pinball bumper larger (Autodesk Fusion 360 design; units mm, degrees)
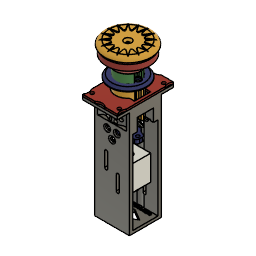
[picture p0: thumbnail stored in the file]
sketch "Base" plane through (0, 0, 0) normal (0, 0, 1) x axis (1, 0, 0)
  line L1 (-14, 14) -> (-14, 0)
  line L2 (14, 14) -> (-14, 14)
  line L3 (14, -14) -> (14, 14)
  line L4 (-14, -14) -> (14, -14)
  line L5 (-14, 0) -> (-14, -14)
  line L6 (7.0005, 2.407) -> (7.0005, 3.4695)
  line L7 (-0.5917, 4.9649) -> (-0.5917, 14)
  line L8 (-0.5917, -12.486) -> (-0.5917, -4.9649)
  line L9 (0.5945, -4.9645) -> (0.5945, -12.4859)
  line L10 (0.5945, 14) -> (0.5945, 4.9645)
  line L11 (-12.5, -0.0109) -> (12.5, 0.0078)
  line L12 (12.013, 3.4552) -> (7.0005, 3.4695)
  line L13 (7.0031, -3.4721) -> (7.0023, -2.3954)
  line L14 (7.401, -3.1) -> (7.4011, 0)
  line L15 (7.4011, 0) -> (7.4011, 3.1)
  line L16 (11.6962, -3.1) -> (7.401, -3.1)
  line L17 (11.6962, 3.1) -> (7.4011, 3.1)
  line L18 (-11.6962, -3.1) -> (-7.401, -3.1)
  line L19 (-11.6962, 3.1) -> (-7.4011, 3.1)
  line L20 (-12, 3.5) -> (-7, 3.5)
  line L21 (-7.401, -3.1) -> (-7.4011, 0)
  line L22 (-7.4011, 0) -> (-7.4011, 3.1)
  line L23 (-7, 2.3869) -> (-7, 3.5)
  line L24 (12.0092, -3.4684) -> (7.0031, -3.4721)
  line L25 (-12.0109, -3.4625) -> (-7.0057, -3.4709)
  line L26 (-6.9999, -0.0068) -> (-6.9999, 0)
  line L27 (-7.0057, -3.4709) -> (-7.0039, -2.4178)
  circle C1 centre (0, 0) radius 12.5
  circle C2 centre (0, 0) radius 1.25
  circle C3 centre (-11, -11) radius 1.5
  circle C4 centre (-11, 11) radius 1.5
  circle C5 centre (11, -11) radius 1.5
  circle C6 centre (11, 11) radius 1.5
  circle C7 centre (-6, 6) radius 1.25
  circle C8 centre (6, 6) radius 1.35
  circle C9 centre (-6, -6) radius 1.35
  circle C10 centre (6, -6) radius 1.35
  circle C11 centre (-6, 6) radius 2.5
  circle C12 centre (6, 6) radius 2.5
  circle C13 centre (6, -6) radius 2.5
  circle C14 centre (-6, -6) radius 2.5
  circle C15 centre (0, 0) radius 5
  circle C16 centre (0, 7) radius 1
  circle C17 centre (0, -7) radius 1
  circle C18 centre (0.0006, -7) radius 4.25
  circle C19 centre (-0.0006, 7) radius 4.25
  circle C20 centre (0, 0) radius 3
  arc A1 centre (0, 0) radius 12.1 clockwise from (11.6962, 3.1) to (11.6962, -3.1)
  arc A2 centre (0, 0) radius 12.1 between (-11.6962, 3.1) and (-11.6962, -3.1)
  arc A3 centre (-12.5, -0.0109) radius 6 clockwise from (-7, 2.3869) to (-7.0039, -2.4178)
  arc A4 centre (12.5, 0.0078) radius 6 clockwise from (7.0023, -2.3954) to (7.0005, 2.407)
  point P1 (0, 0)
  point P2 (0, 0)
  point P8 (0, 0)
  point P25 (0.5945, -12.4859)
  point P26 (0.5945, 14)
  point P27 (-0.5917, 14)
  point P28 (-0.5917, -12.486)
  point P31 (-0.5917, -4.9649)
  point P32 (0.5945, -4.9645)
  point P33 (-0.5917, 4.9649)
  point P34 (0.5945, 4.9645)
  point P36 (12.5, 0.0078)
  point P37 (-12.5, -0.0109)
  point P38 (12.013, 3.4552)
  point P55 (12.0092, -3.4684)
  point P56 (-12.0109, -3.4625)
  point P57 (-12, 3.5)
  point P58 (-12.5, -0.0109)
  point P60 (-6.9999, -0.0068)
  point P62 (12.5, 0.0078)
  coincident P1 P2
  vertical L1
  perpendicular L1 L2
  perpendicular L2 L3
  perpendicular L3 L4
  perpendicular L4 L5
  coincident P1 P8
  vertical L6
  coincident C1 P25
  coincident L2 P26
  perpendicular L2 L9
  coincident L2 P27
  coincident C1 P28
  perpendicular L2 L7
  coincident C15 P31
  collinear L7 L8
  coincident C15 P32
  collinear L9 L10
  coincident C15 P33
  coincident C15 P34
  concentric C15 C20
  coincident C1 P36
  coincident C1 P37
  coincident C1 P38
  perpendicular L11 L13
  vertical L15
  perpendicular L14 L16
  perpendicular L15 L17
  perpendicular L18 L21
  perpendicular L19 L22
  coincident C1 P55
  perpendicular L13 L24
  coincident C1 P56
  perpendicular L25 L26
  coincident C1 P57
  coincident P37 P58
  coincident L11 P60
  collinear L26 L27
  coincident P36 P62
sketch "Plunger" plane through (0, 0, 0) normal (0, 0, 1) x axis (1, 0, 0)
  line L1 (14, -14) -> (14, 14)
  line L2 (12.7481, -3.0158) -> (7.5017, -3.0072)
  line L3 (12.7481, 3.0158) -> (7.5017, 3.0073)
  line L4 (-12.7519, 3) -> (-7.5011, 3)
  line L5 (-12.7519, -3) -> (-7.501, -3)
  line L6 (-7.5011, 3) -> (-7.501, -3)
  line L7 (7.5017, 3.0073) -> (7.5017, -3.0072)
  circle C1 centre (0, 0) radius 22.5
  circle C2 centre (0, 0) radius 13.1
  circle C3 centre (-10.1289, -0.0235) radius 1.7
  circle C4 centre (10.1371, 0.0235) radius 1.7
  arc A1 centre (-10.1289, -0.0235) radius 4.611 clockwise from (-12.477, -3.9919) to (-12.4953, 3.934)
  arc A2 centre (10.1371, 0.0235) radius 4.6107 clockwise from (12.4752, 3.9974) to (12.4936, -3.9396)
  point P1 (0, 0)
  point P2 (0, 0)
  point P3 (0, 0)
  point P12 (12.7481, -3.0158)
  point P13 (12.7481, 3.0158)
  point P17 (-10.1289, -0.0235)
  point P19 (-10.1289, -0.0235)
  point P20 (-12.477, -3.9919)
  point P21 (-12.4953, 3.934)
  point P18 (10.1371, 0.0235)
  point P22 (10.1371, 0.0235)
  point P23 (12.4936, -3.9396)
  point P24 (12.4752, 3.9974)
  point P16 (-12.7519, -3)
  point P15 (-12.7519, 3)
  coincident P1 P2
  coincident P1 P3
  coincident C2 P12
  coincident C2 P13
  coincident P17 P19
  coincident C2 P20
  coincident C2 P21
  coincident P18 P22
  coincident C2 P23
  coincident C2 P24
  coincident C2 P16
  horizontal L5
  coincident C2 P15
  horizontal L4
extrude "Extrude2" new body sketch "Plunger" profile of C1 C2 L1 A1 A2 blind 15 from offset 31 bodies "Plunger"
extrude "Extrude74" add sketch "Plunger" profile of C2 L2 L3 L4 L5 C3 C4 L6 L7 blind 8 from offset 35
chamfer "Chamfer1" distance 9
extrude "Extrude4" new body sketch "Base" profile of C1 C2 C7 C8 C9 C10 C11 C12 C13 C14 L6 C15 C16 C17 L10 L8 C18 C19 C20 L11 L12 L13 L20 L23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 blind 27.5 from offset 16 bodies "Base"
extrude "Extrude5" add sketch "Base" profile of C7 C8 C9 C10 C11 C12 C13 C14 blind 7 from offset 11
extrude "Extrude6" add sketch "Base" profile of C7 C8 C9 C10 blind 21.5 from offset 22
sketch "Ball Detect" plane through (0, 0, 11) normal (0, 0, -1) x axis (1, 0, 0)
  circle C1 centre (0, 0) radius 1.5
  circle C2 centre (0, 0) radius 19
  circle C3 centre (0, 0) radius 2.25
  circle C4 centre (-6, -6) radius 3
  circle C5 centre (-6, 6) radius 3
  circle C6 centre (6, 6) radius 3
  circle C7 centre (6, -6) radius 3
  circle C8 centre (0, 0) radius 5
  circle C9 centre (-6, 6) radius 4
  circle C10 centre (6, 6) radius 4
  circle C11 centre (-6, -6) radius 4
  circle C12 centre (6, -6) radius 4
  circle C13 centre (0, 0) radius 13
  circle C14 centre (-10.1289, 0.0235) radius 2.75
  circle C15 centre (10.2043, 0) radius 2.75
  circle C16 centre (0, 7) radius 1.75
  circle C17 centre (0, -7) radius 1.75
  point P5 (-6, -6)
  point P6 (-6, -6)
  point P9 (6, 6)
  point P10 (6, 6)
  point P11 (6, -6)
  point P12 (6, -6)
  point P8 (-6, 6)
  point P14 (-6, 6)
  point P19 (-10.1289, 0.0235)
  point P20 (-10.1289, 0.0235)
  point P23 (0, -7)
  point P24 (0, -7)
  concentric C1 C2
  concentric C2 C3
  coincident P5 P6
  coincident P9 P10
  coincident P11 P12
  concentric C2 C8
  coincident P8 P14
  concentric C8 C13
  coincident P19 P20
  coincident P23 P24
  dimension "d558" diameter C2 = 38
extrude "Extrude9" new body sketch "Ball Detect" profile of C1 C2 C3 C4 C5 C6 C7 C8 C9 C10 C11 C12 C13 C14 C15 blind -3 from offset -1 bodies "Ball Detect"
chamfer "Chamfer2" distance 2.4 distance 2.4
chamfer "Chamfer3" distance 0.5 distance 1
chamfer "Chamfer4" distance 0.5 distance 1
sketch "Top" plane through (0, 0, 43.5) normal (0, 0, 1) x axis (-1, 0, 0)
  line L1 (-21, 0) -> (-12.3799, -1.7289)
  line L2 (-21, 0) -> (-12.3799, 1.7289)
  line L3 (-19.4015, -8.0364) -> (-10.5434, -2.0972)
  line L4 (-19.4015, -8.0364) -> (-8.9383, -5.9724)
  line L5 (-14.8492, -14.8492) -> (-8.9383, -5.9724)
  line L6 (-14.8492, -14.8492) -> (-5.9724, -8.9383)
  line L7 (-8.0364, -19.4015) -> (-5.9724, -8.9383)
  line L8 (-8.0364, -19.4015) -> (-2.0972, -10.5434)
  line L9 (0, -21) -> (-2.0972, -10.5434)
  line L10 (0, -21) -> (2.0972, -10.5434)
  line L11 (8.0364, -19.4015) -> (2.0972, -10.5434)
  line L12 (8.0364, -19.4015) -> (5.9724, -8.9383)
  line L13 (14.8492, -14.8492) -> (5.9724, -8.9383)
  line L14 (14.8492, -14.8492) -> (8.9383, -5.9724)
  line L15 (19.4015, -8.0364) -> (8.9383, -5.9724)
  line L16 (19.4015, -8.0364) -> (10.5434, -2.0972)
  line L17 (21, 0) -> (10.5434, -2.0972)
  line L18 (21, 0) -> (10.5434, 2.0972)
  line L19 (19.4015, 8.0364) -> (10.5434, 2.0972)
  line L20 (19.4015, 8.0364) -> (8.9383, 5.9724)
  line L21 (14.8492, 14.8492) -> (8.9383, 5.9724)
  line L22 (14.8492, 14.8492) -> (5.9724, 8.9383)
  line L23 (8.0364, 19.4015) -> (5.9724, 8.9383)
  line L24 (8.0364, 19.4015) -> (2.0972, 10.5434)
  line L25 (0, 21) -> (2.0972, 10.5434)
  line L26 (0, 21) -> (-2.0972, 10.5434)
  line L27 (-8.0364, 19.4015) -> (-2.0972, 10.5434)
  line L28 (-8.0364, 19.4015) -> (-5.9724, 8.9383)
  line L29 (-14.8492, 14.8492) -> (-5.9724, 8.9383)
  line L30 (-14.8492, 14.8492) -> (-8.9383, 5.9724)
  line L31 (-19.4015, 8.0364) -> (-8.9383, 5.9724)
  line L32 (-19.4015, 8.0364) -> (-10.5434, 2.0972)
  line L33 (-12.013, -3.4552) -> (-7.0005, -3.4695)
  line L34 (7, -3.5) -> (12, -3.5)
  line L35 (7, -2.3869) -> (7, -3.5)
  line L36 (7.0057, 3.4709) -> (7.0039, 2.4178)
  line L37 (12.0109, 3.4625) -> (7.0057, 3.4709)
  line L38 (-7.0031, 3.4721) -> (-12.0092, 3.4684)
  line L39 (-7.0023, 2.3954) -> (-7.0031, 3.4721)
  line L40 (-7.0005, -3.4695) -> (-7.0005, -2.407)
  circle C1 centre (0, 0) radius 12.5
  circle C2 centre (0, 0) radius 24
  circle C3 centre (0, 0) radius 1.75
  circle C4 centre (0, 0) radius 21
  circle C5 centre (0, 0) radius 4
  arc A1 centre (0, 0) radius 12.5 clockwise from (12, -3.5) to (-12.013, -3.4552)
  arc A2 centre (12.5, 0.0109) radius 6 clockwise from (7, -2.3869) to (7.0039, 2.4178)
  arc A3 centre (-12.5, -0.0078) radius 6 clockwise from (-7.0023, 2.3954) to (-7.0005, -2.407)
  arc A4 centre (0, 0) radius 12.5 clockwise from (-12.0092, 3.4684) to (12.0109, 3.4625)
  point P1 (0, 0)
  point P2 (0, 0)
  point P3 (0, 0)
  point P6 (-12.3799, -1.7289)
  point P7 (-21, 0)
  point P8 (-12.3799, 1.7289)
  coincident P1 P2
  coincident P1 P3
  concentric C2 C3
  concentric C3 C4
  coincident C1 P6
  coincident C4 P7
  coincident C1 P8
  concentric C1 C5
  dimension "d506" diameter C3 = 3.5
extrude "Extrude13" new body sketch "Top" profile of C1 C2 C3 along normal blind 4 bodies "Top"
extrude "Extrude14" cut sketch "Top" profile of C1 L1 L2 L3 L4 L5 L6 L7 L8 L9 L10 L11 L12 L13 L14 L15 L16 L17 L18 L19 L20 L21 L22 L23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 blind 2 from offset 3
fillet "Fillet2" radius 5
extrude "Extrude15" cut sketch "Top" profile of C3 along normal blind 4
move "Move1"
extrude "Extrude17" cut sketch "Base" profile of C16 C17 L10 L8 blind 35 from offset 12
extrude "Extrude18" add sketch "Base" profile of C2 blind 10 from offset 18
extrude "Extrude19" cut sketch "Base" profile of C2 C11 C12 C13 C14 C15 C16 C17 L10 L8 C18 C19 C20 L11 blind 20 from offset 30
sketch "Pinball Deck" plane through (0, 0, 11) normal (0, 0, -1) x axis (1, 0, 0)
  line L1 (-25, 30) -> (-25, 0)
  line L2 (25, 30) -> (-25, 30)
  line L3 (25, -30) -> (25, 30)
  line L4 (-25, -30) -> (25, -30)
  line L5 (-25, 0) -> (-25, -30)
  circle C1 centre (0, 0) radius 13.5
  circle C2 centre (-14, -23) radius 1.75
  circle C3 centre (-14, 23) radius 1.75
  circle C4 centre (14, 23) radius 1.75
  circle C5 centre (14, -23) radius 1.75
  circle C6 centre (-14, -23) radius 1.25
  circle C7 centre (14, -23) radius 1.25
  circle C8 centre (14, 23) radius 1.25
  circle C9 centre (-14, 23) radius 1.25
  vertical L1
  perpendicular L1 L2
  perpendicular L2 L3
  perpendicular L3 L4
  perpendicular L4 L5
  concentric C2 C6
extrude "Extrude20" new body sketch "Pinball Deck" profile of L1 L2 L3 L4 L5 C1 along normal blind 9 bodies "Deck Section"
move "Move2"
move "Move3"
sketch "Under Deck Bracket" plane through (0, 0, 2) normal (0, 0, -1) x axis (1, 0, 0)
  line L1 (-17.9995, 13.0183) -> (17.9988, 13.0592)
  line L2 (0.0008, -6.0881) -> (-0.0008, -6.0881)
  line L3 (18.0002, -6.0876) -> (15.0003, -6.0878)
  line L4 (-17.9854, 5.8364) -> (-14.9979, 5.8364)
  line L5 (-17.9981, -0.0004) -> (-14.998, -0.0004)
  line L6 (15.0001, 0) -> (17.9998, 0)
  line L7 (1.7205, 12.1453) -> (1.7195, 13.0407)
  line L8 (-17.9988, -29.0044) -> (-17.9998, 28.9956)
  line L9 (17.9985, 16.536) -> (-17.9996, 16.5408)
  line L10 (18.001, -16.536) -> (-17.999, -16.5011)
  line L11 (18, -12.9962) -> (-17.999, -12.999)
  line L12 (15, 16.5364) -> (17.9985, 16.536)
  line L13 (15.0006, -16.5331) -> (14.9996, 16.5364)
  line L14 (-14.9975, 28.996) -> (-14.9975, 29.0001)
  line L15 (-14.9983, -16.504) -> (-14.9977, 16.5374)
  line L16 (-14.9981, -6.0595) -> (-17.9992, -6.0594)
  line L17 (17.9993, 5.8365) -> (14.9999, 5.8365)
  line L18 (-17.9991, -8.3161) -> (-9.5987, -8.3159)
  line L19 (9.5984, -8.3163) -> (18.0004, -8.3163)
  line L20 (-17.9994, 8.328) -> (-9.5881, 8.3281)
  line L21 (17.9991, 8.3438) -> (9.575, 8.3432)
  line L22 (14.9996, 16.5364) -> (10.5635, 11.6148)
  line L23 (-14.9977, 16.5404) -> (-10.5574, 11.6203)
  line L24 (15.0006, -16.5331) -> (10.5496, -11.6274)
  line L25 (-14.9983, -16.504) -> (-10.5589, -11.6189)
  line L26 (18.0002, 28.9864) -> (-17.9998, 28.9956)
  line L27 (18.0012, -29.0136) -> (18.0002, 28.9864)
  line L28 (18.0012, -29.0136) -> (-17.9988, -29.0044)
  line L29 (-17.9994, 5.8364) -> (-17.9854, 5.8364)
  line L30 (-17.999, -16.5011) -> (-17.999, -16.5011)
  line L31 (18.001, -12.9962) -> (18, -12.9962)
  line L32 (18.0009, -8.3163) -> (18.0004, -8.3163)
  line L33 (18.0008, -6.0876) -> (18.0002, -6.0876)
  line L34 (-17.9993, -0.0004) -> (-17.9981, -0.0004)
  line L35 (18.0007, 0) -> (17.9998, 0)
  line L36 (18.0006, 5.8365) -> (17.9993, 5.8365)
  line L37 (18.0006, 8.3438) -> (17.9991, 8.3438)
  line L38 (18.0005, 13.0592) -> (17.9988, 13.0592)
  line L39 (-14.9977, 16.5404) -> (-14.9977, 16.5374)
  line L40 (16.4992, 16.5362) -> (17.9985, 16.536)
  line L41 (17.2489, 16.5361) -> (17.9985, 16.536)
  line L42 (16.4992, 16.5362) -> (17.9985, 16.536)
  line L43 (17.6237, 16.536) -> (17.9985, 16.536)
  line L44 (17.9985, 16.536) -> (18.0004, 16.536)
  line L45 (-7.1901, 13.9568) -> (0, 0)
  line L46 (-10.5574, 11.6203) -> (0, 0)
  line L47 (10.5635, 11.6148) -> (0, 0)
  line L48 (7.1974, 13.953) -> (0, 0)
  line L49 (4.0675, 15.164) -> (0, 0)
  line L50 (0.0042, 15.7) -> (0, 0)
  line L51 (0.0042, 15.7) -> (0, 0)
  line L52 (-4.0595, 15.1661) -> (0, 0)
  line L53 (4.0675, 15.164) -> (0, 0)
  line L54 (2.7304, 15.4608) -> (0, 0)
  line L55 (-2.7222, 15.4622) -> (0, 0)
  line L56 (-4.0595, 15.1661) -> (0, 0)
  circle C1 centre (0, 0) radius 12.7
  circle C2 centre (0, 0) radius 13.5
  circle C3 centre (-14, -23) radius 1.75
  circle C4 centre (14, -23) radius 1.75
  circle C5 centre (-14, 23) radius 1.75
  circle C6 centre (14, 23) radius 1.75
  arc A1 centre (0, 0) radius 15.7 clockwise from (-10.5574, 11.6203) to (10.5635, 11.6148)
  arc A2 centre (0, 0) radius 15.7 clockwise from (10.5496, -11.6274) to (-10.5589, -11.6189)
  arc A3 centre (0, 0) radius 15.7 clockwise from (-2.7222, 15.4622) to (0.0042, 15.7)
  arc A4 centre (-0.01, -0.1136) radius 15.8136 clockwise from (0.0042, 15.7) to (2.7304, 15.4608)
  arc A5 centre (0, 0) radius 15.7 clockwise from (-10.5574, 11.6203) to (-7.1901, 13.9568)
  arc A6 centre (0, 0) radius 15.7 clockwise from (7.1974, 13.953) to (10.5635, 11.6148)
  arc A7 centre (0, 0) radius 15.7 clockwise from (0.0042, 15.7) to (2.7304, 15.4608)
  arc A8 centre (0.0682, -0.7816) radius 16.485 clockwise from (-2.7222, 15.4622) to (0.0042, 15.7)
  arc A9 centre (0, 0) radius 15.7 clockwise from (-10.5574, 11.6203) to (-7.1901, 13.9568)
  arc A10 centre (0, 0) radius 15.7 clockwise from (7.1974, 13.953) to (10.5635, 11.6148)
  arc A11 centre (0, 0) radius 15.7 clockwise from (-2.7222, 15.4622) to (0.0042, 15.7)
  arc A12 centre (0, 0) radius 15.7 clockwise from (-10.5574, 11.6203) to (-7.1901, 13.9568)
  arc A13 centre (0, 0) radius 15.7 clockwise from (0.0042, 15.7) to (2.7304, 15.4608)
  arc A14 centre (0, 0) radius 15.7 clockwise from (7.1974, 13.953) to (10.5635, 11.6148)
  arc A15 centre (0, 0) radius 15.7 clockwise from (2.7304, 15.4608) to (4.0675, 15.164)
  arc A16 centre (0, 0) radius 15.7 clockwise from (-4.0595, 15.1661) to (-2.7222, 15.4622)
  arc A17 centre (-0.01, -0.1136) radius 15.8136 clockwise from (0.0042, 15.7) to (2.7304, 15.4608)
  arc A18 centre (-0.01, -0.1136) radius 15.8136 clockwise from (0.0042, 15.7) to (2.7304, 15.4608)
  arc A19 centre (0.0682, -0.7816) radius 16.485 clockwise from (-2.7222, 15.4622) to (0.0042, 15.7)
  point P1 (0, 0)
  point P3 (0, 0)
  point P10 (1.7195, 13.0407)
  point P21 (-17.9996, 16.5408)
  point P25 (15.0006, -16.5331)
  point P26 (15.0001, 0)
  point P28 (-14.9983, -16.504)
  point P31 (-14.9981, -6.0595)
  point P32 (-14.9979, 5.8364)
  point P33 (-14.998, -0.0004)
  point P35 (14.9999, 5.8365)
  point P36 (9.5984, -8.3163)
  point P38 (-17.9991, -8.3161)
  point P39 (-9.5987, -8.3159)
  point P40 (-9.5881, 8.3281)
  point P41 (-17.9994, 8.328)
  point P42 (9.575, 8.3432)
  point P45 (-17.999, -12.999)
  point P46 (-17.9992, -6.0594)
  point P47 (15.0003, -6.0878)
  point P48 (-17.9995, 13.0183)
  point P49 (0, 0)
  point P52 (0, 0)
  point P56 (18.0012, -29.0136)
  point P57 (18.0002, 28.9864)
  point P59 (18.001, -16.536)
  point P60 (-17.999, -16.5011)
  point P61 (18.0008, -6.0876)
  point P62 (18.0009, -8.3163)
  point P63 (18.001, -12.9962)
  point P64 (-17.9993, -0.0004)
  point P65 (18.0006, 8.3438)
  point P66 (18.0006, 5.8365)
  point P67 (18.0007, 0)
  point P68 (18.0005, 13.0592)
  point P69 (15, 16.5364)
  point P70 (-14.9977, 16.5404)
  point P76 (0, 0)
  point P78 (0, 0)
  point P82 (0.0042, 15.7)
  point P80 (0, 0)
  point P83 (0, 0)
  point P90 (0, 0)
  point P91 (0, 0)
  point P101 (0, 0)
  point P103 (0, 0)
  point P113 (0, 0)
  point P115 (0, 0)
  point P118 (0, 0)
  point P120 (0, 0)
  coincident P1 P3
  coincident L1 P10
  perpendicular L1 L7
  coincident L8 P21
  coincident L10 P25
  horizontal L6
  coincident L13 P26
  coincident L10 P28
  coincident L15 P31
  perpendicular L15 L16
  horizontal L4
  coincident L15 P32
  coincident L15 P33
  perpendicular L5 L15
  coincident L13 P35
  coincident C1 P36
  perpendicular L8 L18
  horizontal L19
  coincident L8 P38
  coincident C1 P39
  coincident C1 P40
  coincident L8 P41
  perpendicular L8 L20
  coincident C1 P42
  coincident L8 P45
  coincident L8 P46
  coincident L13 P47
  coincident L8 P48
  coincident P49 P52
  coincident L28 P56
  coincident L27 P57
  parallel L4 L29
  coincident L27 P59
  perpendicular L8 L30
  coincident L8 P60
  coincident L27 P61
  coincident L27 P62
  coincident L27 P63
  perpendicular L8 L34
  coincident L8 P64
  coincident L27 P65
  coincident L27 P66
  coincident L27 P67
  coincident L27 P68
  coincident L9 P69
  perpendicular L9 L39
  coincident L9 P70
  coincident P49 P76
  coincident P76 P78
  midpoint A1 P82
  coincident P78 P80
  coincident P76 P83
  coincident P90 P91
  coincident P101 P103
  coincident P113 P115
  coincident P49 P118
  coincident P49 P120
extrude "Extrude21" new body sketch "Under Deck Bracket" profile of L1 C1 L7 C2 L11 L13 L15 L18 L19 L20 L21 A1 A2 L22 L23 L24 L25 L39 A15 A16 along normal blind 23 bodies "Under Deck Bracket"
extrude "Extrude22" new body sketch "Under Deck Bracket" profile of L1 C2 L8 L9 L10 L11 L12 L13 L15 A1 A2 L22 L23 L24 L25 L27 L30 L31 L38 L39 L40 L41 L42 L43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 along normal blind 110
sketch "Under Deck Bracket Rear" plane through (0, 0, -108) normal (0, 0, -1) x axis (1, 0, 0)
  line L1 (17.9926, 13.061) -> (17.9916, 16.536)
  line L2 (18.001, -16.536) -> (18, -13)
  line L3 (-17.9995, 13.0183) -> (-17.9996, 16.5408)
  line L4 (18.0004, 16.536) -> (18.0005, 13.0592)
  line L5 (18.001, -12.9962) -> (18.001, -16.536)
  line L6 (18, -12.9962) -> (18.001, -12.9962)
  line L7 (-17.999, -16.5011) -> (-17.999, -12.999)
  line L8 (-17.999, -16.5011) -> (-17.999, -16.5011)
  line L9 (-17.9995, 13.0183) -> (-17.9996, 16.5408)
  line L10 (-17.999, -16.5011) -> (-17.999, -12.999)
  line L11 (18.001, -16.536) -> (18.0004, 16.536)
  line L12 (-17.999, -16.5011) -> (-17.9996, 16.5408)
  line L13 (18.001, -16.536) -> (-17.999, -16.5011)
  line L14 (17.9916, 16.536) -> (-17.9996, 16.5408)
  line L15 (18.0004, 16.536) -> (-17.9996, 16.5408)
  line L16 (-3.5137, 13.0347) -> (-17.9995, 13.0183)
  line L17 (18.0005, 13.0592) -> (3.4841, 13.0427)
  line L18 (3.6496, -12.9973) -> (18, -12.9962)
  line L19 (-17.999, -12.999) -> (-3.6476, -12.9979)
  line L20 (0, -7) -> (-12, 0)
  line L21 (12, 0) -> (0, -7)
  line L22 (0, 7) -> (12, 0)
  line L23 (-12, 0) -> (0, 7)
  curve K1
  curve K2
  curve K3
  curve K4
  curve K5
  curve K6
  curve K7
  curve K8
  arc A1 centre (0, 0) radius 13.5 clockwise from (-3.5137, 13.0347) to (3.4841, 13.0427)
  arc A2 centre (0, 0) radius 13.5 clockwise from (3.6496, -12.9973) to (-3.6476, -12.9979)
  point P9 (-17.9996, 16.5408)
  point P22 (-17.9996, 16.5408)
  point P16 (-17.999, -12.999)
  point P23 (-17.999, -12.999)
  point P18 (18.0004, 16.536)
  point P24 (18.0004, 16.536)
  point P13 (18.001, -16.536)
  point P25 (18.001, -16.536)
  point P26 (-17.9996, 16.5408)
  point P12 (-17.999, -16.5011)
  point P27 (-17.999, -16.5011)
  point P28 (18.001, -16.536)
  point P14 (-17.9995, 13.0183)
  point P29 (-17.9995, 13.0183)
  point P17 (18.0005, 13.0592)
  point P30 (18.0005, 13.0592)
  point P32 (3.4841, 13.0427)
  point P15 (18, -12.9962)
  point P34 (18, -12.9962)
  point P36 (-3.6476, -12.9979)
  point P31 (0, 0)
  point P35 (0, 0)
  coincident P9 P22
  parallel L3 L9
  coincident P16 P23
  coincident P18 P24
  coincident P13 P25
  coincident P9 P26
  coincident P12 P27
  coincident P13 P28
  coincident P14 P29
  coincident P17 P30
  coincident P32 L16
  collinear L16 L17
  coincident P15 P34
  coincident P36 L18
  coincident P31 P35
  collinear L18 L19
  parallel L20 L22
  parallel L21 L23
  dimension "d547" Text1-Height = 4
  dimension "d553" Text2-Height = 3
combine "Combine1" bodies "Plunger (1)", "Under Deck Bracket"
sketch "Solenoid 22mm long" plane through (0, 0, 0) normal (0, 1, 0) x axis (1, 0, 0)
  line L1 (-22, 0) -> (0, 0)
  line L2 (-22, 26) -> (-22, 0)
  line L3 (0, 26) -> (-22, 26)
  line L4 (0, 0) -> (0, 26)
  point P1 (0, 0)
  point P2 (0, 0)
  point P6 (0, 0)
  coincident P1 P2
  horizontal L1
  perpendicular L1 L2
  perpendicular L2 L3
  coincident P1 P6
  perpendicular L1 L4
extrude "Extrude24" new body sketch "Solenoid 22mm long" along normal blind 25 bodies "Solenoid 22mm long"
move "Move9"
move "Move10"
move "Move11"
sketch "Solenoid 22mm long top" plane through (0, 0, -40) normal (0, 0, 1) x axis (-1, 0, 0)
  line L1 (-11, 12.5) -> (11, 12.5)
  line L2 (-11, -12.5) -> (-11, 12.5)
  line L3 (11, -12.5) -> (-11, -12.5)
  line L4 (11, 12.5) -> (11, -12.5)
  circle C1 centre (0, 0) radius 4
  circle C2 centre (0, 0) radius 4.4
  point P1 (0, 0)
  point P6 (0, 0)
  coincident P1 P6
  concentric C1 C2
extrude "Extrude25" add sketch "Solenoid 22mm long top" profile of C1 along normal blind 18
move "Move12"
sketch "Solenoid 22mm long side" plane through (0, -12.5, 0) normal (0, -1, 0) x axis (1, 0, 0)
  line L1 (7.5, -77.5) -> (7.5, -62.5)
  line L2 (4.5, -62.5) -> (4.5, -77.5)
  line L3 (-4.5, -62.5) -> (-4.5, -47.5)
  line L4 (-7.5, -47.5) -> (-7.5, -62.5)
  circle C1 centre (-6, -60) radius 1.5
  circle C2 centre (6, -75) radius 1.5
  arc A1 centre (6, -62.5) radius 1.5 clockwise from (4.5, -62.5) to (7.5, -62.5)
  arc A2 centre (6, -77.5) radius 1.5 clockwise from (7.5, -77.5) to (4.5, -77.5)
  arc A3 centre (-6, -47.5) radius 1.5 clockwise from (-7.5, -47.5) to (-4.5, -47.5)
  arc A4 centre (-6, -62.5) radius 1.5 clockwise from (-4.5, -62.5) to (-7.5, -62.5)
extrude "Extrude26" cut sketch "Solenoid 22mm long side" along normal blind 10
extrude "Extrude28" cut sketch "Solenoid 22mm long top" profile of C1 C2 against normal blind 20
move "Move13"
move "Move14"
move "Move15"
sketch "Solenoid 37mm long side" plane through (0, -12.5, 0) normal (0, -1, 0) x axis (1, 0, 0)
  line L1 (11, -74) -> (-11, -74)
  line L2 (-11, -100) -> (11, -100)
  line L3 (-11, -63) -> (-11, -100)
  line L4 (11, -63) -> (11, -100)
  line L5 (-11, -63) -> (11, -63)
  line L6 (5.5, -58.5006) -> (5.4939, -74.365)
  line L7 (2.5, -58.5006) -> (2.5061, -74.365)
  line L8 (-2.5, -58.5006) -> (-2.5061, -74.365)
  line L9 (-5.5, -58.5006) -> (-5.4939, -74.365)
  line L10 (-2.5, -78.5003) -> (-2.503, -94.4045)
  line L11 (5.5, -78.5) -> (5.5, -94.5)
  line L12 (2.5, -94.4995) -> (2.5057, -78.6307)
  line L13 (-5.5, -78.5) -> (-5.5, -94.5)
  circle C1 centre (-4, -71.5) radius 1.5
  circle C2 centre (4, -71.5) radius 1.5
  circle C3 centre (-4, -91.5) radius 1.5
  circle C4 centre (4, -91.5) radius 1.5
  arc A1 centre (4, -94.5) radius 1.5 clockwise from (5.5, -94.5) to (2.5, -94.4995)
  arc A2 centre (4, -78.5) radius 1.5 clockwise from (2.5057, -78.6307) to (5.5, -78.5)
  arc A3 centre (-4, -78.5) radius 1.5 clockwise from (-5.5, -78.5) to (-2.5, -78.5003)
  arc A4 centre (-4, -94.5) radius 1.5 clockwise from (-2.503, -94.4045) to (-5.5, -94.5)
  arc A5 centre (-4, -58.5) radius 1.5 clockwise from (-5.5, -58.5006) to (-2.5, -58.5006)
  arc A6 centre (-4, -74.5) radius 1.5 clockwise from (-2.5061, -74.365) to (-5.4939, -74.365)
  arc A7 centre (4, -74.5) radius 1.5 clockwise from (5.4939, -74.365) to (2.5061, -74.365)
  arc A8 centre (4, -58.5) radius 1.5 clockwise from (2.5, -58.5006) to (5.5, -58.5006)
  point P37 (2.5, -94.4995)
  point P40 (2.5, -94.4995)
  tangent L6 A8
  tangent L7 A8
  tangent L8 A5
  tangent L9 A5
  tangent L10 A3
  tangent L11 A2
  coincident P37 A1
  tangent L12 A1
  tangent L13 A3
  coincident L12 P40
extrude "Extrude31" new body sketch "Solenoid 37mm long side" profile of L1 L2 C1 C2 C3 C4 L3 L4 L5 against normal blind 26 bodies "Solenoid 37mm long"
sketch "Solenoid 37mm long top" plane through (0, 0, -63) normal (0, 0, 1) x axis (-1, 0, 0)
  line L1 (-11, 12.5) -> (11, 12.5)
  line L2 (-11, -13.5) -> (-11, 12.5)
  line L3 (11, -13.5) -> (-11, -13.5)
  line L4 (11, 12.5) -> (11, -13.5)
  line L5 (-11, 12.5) -> (11, 12.5)
  line L6 (11, -13.5) -> (-11, -13.5)
  line L7 (-11, -13.5) -> (-11, 12.5)
  line L8 (11, 12.5) -> (11, -13.5)
  circle C1 centre (0, 0) radius 4
  circle C2 centre (0, 0) radius 4.25
  point P1 (0, 0)
  point P6 (0, 0)
  point P7 (0, 0)
  coincident P1 P6
  coincident P1 P7
extrude "Extrude32" add sketch "Solenoid 37mm long top" profile of C1 along normal blind 25
move "Move16"
move "Move17"
move "Move18"
move "Move19"
move "Move20"
extrude "Extrude33" cut sketch "Solenoid 37mm long side" profile of C1 C3 C4 L8 L9 L10 L12 along normal blind 15 and against normal blind 30
extrude "Extrude35" cut sketch "Solenoid 37mm long side" profile of C1 C3 C4 A5 A3 A2 A1 A4 A6 L8 L9 L10 L11 L12 L13 along normal blind 30 and against normal blind 30
extrude "Extrude36" cut sketch "Solenoid 37mm long side" profile of C2 A8 A7 L6 L7 against normal blind 40
extrude "Extrude37" add sketch "Under Deck Bracket" profile of L1 C2 L8 L9 L12 L13 L15 L20 L27 L38 L40 L41 L42 L43 L44 along normal blind 3
move "Move21"
move "Move22"
move "Move23"
move "Move24"
move "Move25"
extrude "Extrude47" cut sketch "Solenoid 22mm long side" profile of C1 C2 against normal blind 6
extrude "Extrude49" cut sketch "Plunger" profile of C3 C4 along normal blind 200
move "Move26"
sketch "Tactile Switch SR1112A" plane through (0, 0, 0) normal (0, 0, 1) x axis (1, 0, 0)
  line L1 (-3, -3) -> (-3, 3)
  line L2 (3, -3) -> (-3, -3)
  line L3 (3, 3) -> (3, -3)
  line L4 (-3, 3) -> (3, 3)
  line L5 (-2, -4) -> (-2, -3)
  line L6 (-2.5, -4) -> (-2, -4)
  line L7 (-2.5, -3) -> (-2.5, -4)
  line L8 (2.5, -4) -> (2.5, -3)
  line L9 (2, -4) -> (2.5, -4)
  line L10 (2, -3) -> (2, -4)
  line L11 (2.5, 4) -> (2.5, 3)
  line L12 (2, 4) -> (2.5, 4)
  line L13 (2, 3) -> (2, 4)
  line L14 (-2, 4) -> (-2, 3)
  line L15 (-2.5, 4) -> (-2, 4)
  line L16 (-2.5, 3) -> (-2.5, 4)
  circle C1 centre (0, 0) radius 1.75
  point P6 (-2, -3)
  point P9 (-2.5, -3)
  point P10 (2.5, -3)
  point P13 (2, -3)
  point P14 (2.5, 3)
  point P17 (2, 3)
  point P18 (-2, 3)
  point P21 (-2.5, 3)
  point P1 (0, 0)
  point P22 (0, 0)
  vertical L1
  perpendicular L1 L2
  perpendicular L2 L3
  coincident L2 P6
  perpendicular L2 L5
  perpendicular L5 L6
  coincident L2 P9
  perpendicular L2 L7
  coincident L2 P10
  perpendicular L2 L8
  perpendicular L8 L9
  coincident L2 P13
  perpendicular L2 L10
  coincident L4 P14
  perpendicular L4 L11
  perpendicular L11 L12
  coincident L4 P17
  perpendicular L4 L13
  coincident L4 P18
  perpendicular L4 L14
  perpendicular L14 L15
  coincident L4 P21
  perpendicular L4 L16
  coincident P1 P22
extrude "Extrude52" new body sketch "Tactile Switch SR1112A" profile of L1 L2 L3 L4 C1 along normal blind 3.6 bodies "Tactile Switch SR1112A"
extrude "Extrude54" add sketch "Tactile Switch SR1112A" profile of L2 L4 L5 L6 L7 L8 L9 L10 L11 L12 L13 L14 L15 L16 along normal blind 1
sketch "Base Lower" plane through (0, 0, 11) normal (0, 0, 1) x axis (1, 0, 0)
  line L1 (7.0031, -2.9721) -> (7.0005, 2.9695)
  line L2 (-2.7511, 5.4979) -> (-4.5, 1.5997)
  line L3 (2.7467, 5.4851) -> (-2.7511, 5.4979)
  line L4 (4.5, 1.6215) -> (2.7467, 5.4851)
  line L5 (4.5, -1.5938) -> (4.5, 1.6215)
  line L6 (2.7506, -5.505) -> (4.5, -1.5938)
  line L7 (-2.7506, -5.505) -> (2.7506, -5.505)
  line L8 (-4.5, -1.5937) -> (-2.7506, -5.505)
  line L9 (-4.5, 1.5997) -> (-4.5, -1.5937)
  line L10 (12.1422, 2.9695) -> (7.0005, 2.9695)
  line L11 (12.1415, -2.9721) -> (7.0031, -2.9721)
  line L12 (-12.14, 2.9785) -> (-7, 2.9785)
  line L13 (-12.1418, -2.9709) -> (-7.0053, -2.9709)
  line L14 (-7.0053, -2.9709) -> (-7.0004, 2.9785)
  circle C1 centre (0, 7) radius 1
  circle C2 centre (0, -7) radius 1
  circle C3 centre (6, -6) radius 2.7
  circle C4 centre (-6, -6) radius 2.6
  circle C5 centre (-6, 6) radius 2.7
  circle C6 centre (6, 6) radius 2.7
  circle C7 centre (-6, 6) radius 1.6
  circle C8 centre (6, 6) radius 1.6
  circle C9 centre (6, -6) radius 1.6
  circle C10 centre (-6, -6) radius 1.6
  circle C11 centre (0, -4.5) radius 1
  circle C12 centre (0, 4.5) radius 1
  circle C13 centre (6, 6) radius 1.35
  circle C14 centre (6, 6) radius 2.5
  circle C15 centre (6, 6) radius 3.05
  circle C16 centre (-6, 6) radius 3.05
  circle C17 centre (6, -6) radius 3.05
  circle C18 centre (-6, -6) radius 3.05
  circle C19 centre (0, 0) radius 1.45
  circle C20 centre (0, 0) radius 3.1
  arc A1 centre (0, 0) radius 12.5 clockwise from (12.1415, -2.9721) to (-12.1418, -2.9709)
  arc A2 centre (0, 0) radius 12.5 clockwise from (-12.14, 2.9785) to (12.1422, 2.9695)
  point P2 (0, 7)
  point P3 (0, 7)
  point P4 (0, -7)
  point P5 (0, -7)
  point P6 (6, -6)
  point P7 (6, -6)
  point P37 (-7.0004, 2.9785)
  point P41 (12.1422, 2.9695)
  coincident P2 P3
  coincident P4 P5
  coincident P6 P7
  concentric C5 C7
  vertical L5
  perpendicular L5 L7
  perpendicular L7 L9
  concentric C6 C15
  horizontal L10
  horizontal L11
  horizontal L12
  horizontal L13
  coincident L12 P37
  coincident P41 A1
  concentric A1 A2
  dimension "d546" diameter C19 = 2.9
extrude "Extrude59" add sketch "Tactile Switch SR1112A" profile of C1 along normal blind 4.3
move "Move27"
fillet "Fillet5" radius 1
fillet "Fillet6" radius 2
extrude "Extrude63" new body sketch "Base Lower" profile of L1 L14 C1 C2 C3 C4 C5 C6 C7 C8 C9 C10 L2 L3 L4 L5 L6 L7 L8 L9 C12 C14 C15 C16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 against normal blind 4.1 bodies "Base Lower"
extrude "Extrude65" new body sketch "Base Lower" profile of L1 L14 C1 C2 L2 L3 L4 L5 L6 L7 L8 L9 C11 C12 C15 C16 C17 C18 C19 C20 L10 L11 L12 L13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 blind -27.9 from offset -4.1 bodies "Base Lower"
combine "Combine4" bodies "Base Lower"
move "Move28"
extrude "Extrude66" add sketch "Under Deck Bracket" profile of L1 C3 C4 C5 C6 L8 L9 L10 L11 L12 A1 A2 L22 L23 L24 L25 L26 L27 L28 L30 L40 L41 L42 L43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 along normal blind 3
extrude "Extrude67" new body sketch "Under Deck Bracket" profile of L1 L3 L4 L5 L6 L8 L11 L13 L15 L16 L17 L18 L19 L20 L21 L27 L29 L31 L32 L33 L34 L35 L36 L37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 along normal blind 11
combine "Combine7" bodies "Plunger (1)"
extrude "Extrude68" cut sketch "Under Deck Bracket" profile of C5 C6 along normal blind 10
extrude "Extrude69" cut sketch "Under Deck Bracket" profile of L1 L10 L11 A1 A2 L22 L23 L24 L25 blind 18 from offset 3
extrude "Extrude70" cut sketch "Under Deck Bracket" profile of L1 L9 A1 L22 L23 blind 18 from offset 3
extrude "Extrude71" add sketch "Under Deck Bracket Rear" profile of L3 L4 L5 L6 L9 L11 L12 L13 L14 L17 L15 A1 L19 A2 L20 L21 L22 L23 along normal blind 3
extrude "Extrude72" add sketch "Under Deck Bracket" profile of L1 L8 L11 L13 L15 L18 L19 L20 L21 L27 L31 L32 L37 L38 along normal blind 24
move "Move29"
extrude "Extrude73" cut sketch "Base" profile of C16 C17 L10 L8 along normal blind 20
work_plane "WorkPlane1"
sketch "Holes Left" plane through (7.1974, -13.953, 0) normal (0.4584, -0.8887, 0) x axis (0.8887, 0.4584, 0)
  circle C1 centre (0, -8) radius 1.6
  circle C2 centre (0, -14) radius 1.6
  circle C3 centre (0, -7.5) radius 1.25
  circle C4 centre (0, -13) radius 1.25
  circle C5 centre (0, -3.5) radius 1.6
  circle C6 centre (0, -3.5) radius 1.25
  circle C7 centre (0, -16) radius 1.25
work_plane "WorkPlane2"
sketch "Holes Right" plane through (-7.1901, -13.9568, 0) normal (-0.458, -0.889, 0) x axis (0.889, -0.458, 0)
  circle C1 centre (0, -8) radius 1.6
  circle C2 centre (0, -14) radius 1.6
  circle C3 centre (0, -7.5) radius 1.25
  circle C4 centre (0, -13) radius 1.25
  circle C5 centre (0, -3.5) radius 1.25
  circle C6 centre (0, -3.5) radius 1.6
  circle C7 centre (0, -16) radius 1.25
  point P2 (0, -8)
  point P3 (0, -8)
  point P4 (0, -14)
  point P5 (0, -14)
  coincident P2 P3
  coincident P4 P5
work_plane "WorkPlane3"
sketch "Holes Mid Right" plane through (-2.7222, -15.4622, 0) normal (-0.1734, -0.9849, 0) x axis (0.9849, -0.1734, 0)
  circle C1 centre (0, -5) radius 1.6
  circle C2 centre (0, -11) radius 1.6
  circle C3 centre (0, -17) radius 1.6
  circle C4 centre (0, -5.5) radius 1.25
  circle C5 centre (0, -12) radius 1.25
  circle C6 centre (0, -18.5) radius 1.25
  circle C7 centre (0, -2.5) radius 1.25
  point P2 (0, -5)
  point P3 (0, -5)
  coincident P2 P3
work_plane "WorkPlane4"
sketch "Holes Mid Left" plane through (2.7304, -15.4608, 0) normal (0.1739, -0.9848, 0) x axis (0.9848, 0.1739, 0)
  circle C1 centre (0, -5) radius 1.6
  circle C2 centre (0.2031, -10.6713) radius 1.6
  circle C3 centre (0, -17) radius 1.6
  circle C4 centre (0, -5.5) radius 1.25
  circle C5 centre (0.2, -12) radius 1.25
  circle C6 centre (0, -18.5) radius 1.25
  circle C7 centre (0, -2.5) radius 1.25
  point P2 (0, -5)
  point P3 (0, -5)
  point P4 (0.2031, -10.6713)
  point P5 (0.2031, -10.6713)
  coincident P2 P3
  coincident P4 P5
extrude "Extrude75" cut sketch "Holes Right" profile of C1 C2 C3 C4 C5 C6 against normal blind 50
extrude "Extrude76" cut sketch "Holes Mid Right" profile of C1 C2 C3 C4 C5 C6 along a picked direction blind -50
extrude "Extrude77" cut sketch "Holes Mid Left" profile of C1 C2 C3 C4 C5 C6 along a picked direction blind -50
extrude "Extrude78" cut sketch "Holes Left" profile of C1 C2 C3 C4 C5 C6 against normal blind 50
extrude "Extrude79" cut sketch "Holes Left" profile of C1 C2 C3 C4 C6 against normal blind 10
extrude "Extrude80" cut sketch "Holes Right" profile of C1 C2 C3 C4 C5 against normal blind 10
extrude "Extrude81" cut sketch "Holes Right" profile of C1 C2 C3 C4 C5 blind -9 from offset -22
extrude "Extrude82" cut sketch "Holes Left" profile of C1 C2 C3 C4 C6 blind -9 from offset -22
extrude "Extrude83" cut sketch "Holes Right" profile of C2 C7 against normal blind 10
extrude "Extrude84" cut sketch "Holes Right" profile of C2 C7 blind -10 from offset -21
extrude "Extrude85" cut sketch "Holes Left" profile of C2 C7 blind -10 from offset -21
extrude "Extrude86" cut sketch "Holes Left" profile of C2 C7 against normal blind 10
extrude "Extrude87" cut sketch "Holes Mid Left" profile of C1 C2 C3 C4 C5 C6 against normal blind 10
extrude "Extrude88" cut sketch "Holes Mid Left" profile of C1 C2 C3 C4 C5 C6 blind -10 from offset -21
extrude "Extrude89" cut sketch "Holes Mid Left" profile of C1 C7 against normal blind 10
extrude "Extrude90" cut sketch "Holes Mid Left" profile of C1 C7 blind -10 from offset -21
extrude "Extrude91" cut sketch "Holes Mid Right" against normal blind 10
extrude "Extrude92" cut sketch "Holes Mid Right" blind -10 from offset -21
extrude "Extrude93" cut sketch "Pinball Deck" profile of C6 C7 C8 C9 along normal blind 20 and against normal blind 10
chamfer "Chamfer32" distance 0.6
chamfer "Chamfer33" distance 0.5
chamfer "Chamfer34" distance 0.5
chamfer "Chamfer35" distance 0.5
sketch "Plunger Coupling" plane through (0, 0, -38) normal (0, 0, 1) x axis (-1, 0, 0)
  line L1 (13.5, 0) -> (13.5, 4.5)
  line L2 (13.5, -4.5) -> (13.5, 0)
  line L3 (-13.5, -4.5) -> (-13.5, 4.5)
  line L4 (13.5, -4.5) -> (-13.5, -4.5)
  line L5 (-13.5, 4.5) -> (13.5, 4.5)
  line L6 (5, -9) -> (5, -4.5)
  line L7 (-5, -9) -> (5, -9)
  line L8 (-5, -4.5) -> (-5, -9)
  line L9 (5, 9) -> (5, 4.5)
  line L10 (-5, 9) -> (5, 9)
  line L11 (-5, 4.5) -> (-5, 9)
  line L12 (-1.6, -4.5) -> (-1.6, -9)
  line L13 (1.6, -4.5) -> (1.6, -9)
  line L14 (-1.6, 4.5) -> (-1.6, 9)
  line L15 (1.6, 9) -> (1.6, 4.5)
  circle C1 centre (0, 0) radius 4
  circle C2 centre (-10.1371, -0.0235) radius 1.7
  circle C3 centre (10.1289, 0.0235) radius 1.7
  circle C4 centre (0, 0) radius 4.25
  point P3 (-10.1371, -0.0235)
  point P4 (-10.1371, -0.0235)
  point P5 (10.1289, 0.0235)
  point P6 (10.1289, 0.0235)
  point P13 (5, -4.5)
  point P16 (-5, -4.5)
  point P17 (5, 4.5)
  point P20 (-5, 4.5)
  point P25 (-1.6, 9)
  point P27 (1.6, 4.5)
  point P28 (1.6, 9)
  coincident P3 P4
  coincident P5 P6
  concentric C1 C4
  parallel L1 L2
  coincident L4 P13
  perpendicular L4 L6
  perpendicular L6 L7
  coincident L4 P16
  perpendicular L4 L8
  coincident L5 P17
  perpendicular L5 L9
  perpendicular L9 L10
  coincident L5 P20
  perpendicular L5 L11
  coincident L10 P25
  coincident L5 P27
  coincident L10 P28
  perpendicular L10 L15
extrude "Extrude95" new body sketch "Plunger Coupling" profile of C2 C3 C4 L1 L2 L3 L4 L5 L6 L7 L8 L9 L10 L11 L12 L13 L14 L15 along normal blind 4 bodies "Plunger Coupling"
extrude "Extrude96" add sketch "Plunger Coupling" profile of C4 L4 L5 L6 L7 L8 L9 L10 L11 L12 L13 L14 L15 against normal blind 9
sketch "Plunger Coupling Cross Holes" plane through (0, 9, 0) normal (0, 1, 0) x axis (-1, 0, 0)
  line L1 (5, -34) -> (5, -47)
  line L2 (-5, -34) -> (5, -34)
  line L3 (-5, -47) -> (-5, -34)
  line L4 (5, -47) -> (-5, -47)
  circle C1 centre (0, -43.5) radius 1.6
extrude "Extrude97" cut sketch "Plunger Coupling Cross Holes" profile of C1 against normal blind 20
fillet "Fillet14" radius 4
fillet "Fillet15" radius 3
fillet "Fillet16" radius 3
fillet "Fillet17" radius 2
fillet "Fillet18" radius 9
fillet "Fillet19" radius 0.6
fillet "Fillet21" radius 2
extrude "Extrude98" cut sketch "Base Lower" profile of C3 C4 C5 C6 C7 C8 C9 C10 C14 C15 C16 C17 C18 against normal blind 0.6
extrude "Extrude99" cut sketch "Plunger" profile of C2 L1 A1 A2 blind 39 from offset 37
fillet "Fillet25" radius 1
fillet "Fillet27" radius 1
move "Move30"
move "Move31"
move "Move32"
move "Move33"
move "Move34"
sketch "Sketch25" plane through (-0.016, 16.5185, 0) normal (-0.001, 1, 0) x axis (-1, -0.001, 0)
  line L1 (5.4779, -74.365) -> (5.484, -58.5006)
  line L2 (2.484, -58.5006) -> (2.4901, -74.365)
  line L3 (2.484, -78.5003) -> (2.4871, -94.4045)
  line L4 (5.484, -94.5) -> (5.484, -78.5)
  line L5 (-2.516, -94.4995) -> (-2.5217, -78.6307)
  line L6 (-5.516, -78.5) -> (-5.516, -94.5)
  line L7 (-5.516, -58.5006) -> (-5.5099, -74.365)
  line L8 (-2.5221, -74.365) -> (-2.516, -58.5006)
  line L9 (14.9823, -19) -> (14.9823, -1)
  line L10 (-15.0166, -19) -> (14.9823, -19)
  line L11 (-15.0166, -1) -> (-15.0166, -19)
  line L12 (-18.017, -1) -> (-15.0166, -1)
  line L13 (-18.017, -111) -> (-18.017, -1)
  line L14 (17.983, -111) -> (-18.017, -111)
  line L15 (17.983, -108) -> (17.983, -111)
  line L16 (17.983, -1) -> (17.983, -108)
  line L17 (14.9823, -1) -> (17.983, -1)
  closed curve K1 centre (3.984, -74.5)
  closed curve K2 centre (3.984, -58.5)
  closed curve K3 centre (3.984, -78.5)
  closed curve K4 centre (3.984, -94.5)
  closed curve K5 centre (-4.016, -94.5)
  closed curve K6 centre (-4.016, -78.5)
  closed curve K7 centre (-4.016, -58.5)
  closed curve K8 centre (-4.016, -74.5)
  circle C1 centre (-5, -26) radius 2.5
  circle C2 centre (5, -26) radius 2.5
  circle C3 centre (0, -34) radius 2.5
extrude "Extrude100" cut sketch "Sketch25" profile of C1 C2 C3 against normal blind 50
fillet "Fillet28" radius 1
chamfer "Chamfer36" distance 2
extrude "Extrude101" cut sketch "Base Lower" profile of C19 against normal blind 50
extrude "Extrude102" cut sketch "Base Lower" profile of C19 C20 blind -40 from offset -7.5
chamfer "Chamfer37" distance 1.6
fillet "Fillet29" radius 1.2
chamfer "Chamfer39" distance 2.2
fillet "Fillet30" radius 1.2
fillet "Fillet31" radius 1.2
fillet "Fillet32" radius 1.2
extrude "Extrude104" cut sketch "Under Deck Bracket Rear" along normal blind 1
extrude "Extrude105" add sketch "Under Deck Bracket Rear" blind 1
sphere_primitive "SpherePrimitive1" Diameter 20
move_face "MoveFace1"
move_face "MoveFace2"
move "Move40"
move_face "MoveFace3"
move_face "MoveFace4"
sketch "Shim_For_Base" plane through (0, 0, 2) normal (0, 0, 1) x axis (-1, 0, 0)
  line L1 (9.5987, -8.3159) -> (14.9982, -8.316)
  line L2 (-15.0003, -8.3163) -> (-9.5984, -8.3163)
  line L3 (-14.9998, 8.3436) -> (-15.0003, -8.3163)
  line L4 (-9.575, 8.3432) -> (-14.9998, 8.3436)
  line L5 (14.9979, 8.3281) -> (9.5881, 8.3281)
  line L6 (14.9982, -8.316) -> (14.9979, 8.3281)
  line L7 (17.9998, 28.9956) -> (17.9988, -29.0044)
  line L8 (-18.0002, 28.9864) -> (17.9998, 28.9956)
  line L9 (-18.0012, -29.0136) -> (-18.0002, 28.9864)
  line L10 (17.9988, -29.0044) -> (-18.0012, -29.0136)
  line L11 (-5.4005, -29.0104) -> (-18.0012, -29.0136)
  line L12 (17.9988, -29.0044) -> (5.3316, -29.0076)
  line L13 (-18.0012, -29.0136) -> (-18.0012, -28.9994)
  line L14 (-18.0002, 28.4454) -> (-18.0002, 28.9864)
  line L15 (-18.0011, -20.4484) -> (-18.0004, 19.8969)
  line L16 (-5.2979, 28.9897) -> (-18.0002, 28.9864)
  line L17 (17.9998, 28.9956) -> (5.2344, 28.9924)
  line L18 (17.9998, 28.5388) -> (17.9998, 28.9956)
  line L19 (17.9989, -20.3574) -> (17.9996, 19.8039)
  arc A1 centre (0, 0) radius 12.7 clockwise from (9.5987, -8.3159) to (-9.5984, -8.3163)
  arc A2 centre (0, 0) radius 12.7 clockwise from (-9.575, 8.3432) to (9.5881, 8.3281)
  circle C1 centre (-14, -23) radius 1.75
  circle C2 centre (14, -23) radius 1.75
  circle C3 centre (14, 23) radius 1.75
  circle C4 centre (-14, 23) radius 1.75
  circle C5 centre (34.2569, 0.0412) radius 6.25
  circle C6 centre (-0.0331, -34.2488) radius 6.25
  circle C7 centre (-0.0331, 34.3312) radius 6.25
  circle C8 centre (-24.1631, -24.7238) radius 6.25
  circle C9 centre (-24.1631, 24.1712) radius 6.25
  circle C10 centre (24.0969, -24.7238) radius 6.25
  circle C11 centre (-34.3231, 0.0412) radius 6.25
  circle C12 centre (24.0969, 24.1712) radius 6.25
  circle C13 centre (0, 0) radius 13
  arc A3 centre (-0.0331, 34.3312) radius 7.5 clockwise from (5.2344, 28.9924) to (-5.2979, 28.9897)
  arc A4 centre (24.0969, 24.1712) radius 7.5 clockwise from (17.9996, 19.8039) to (17.9998, 28.5388)
  arc A5 centre (24.0969, -24.7238) radius 7.5 clockwise from (17.9384, -29.0044) to (17.9989, -20.3574)
  arc A6 centre (-0.0331, -34.2488) radius 7.5 clockwise from (-5.4005, -29.0104) to (5.3316, -29.0076)
  arc A7 centre (-24.1631, -24.7238) radius 7.5 clockwise from (-18.0011, -20.4484) to (-18.0012, -28.9994)
  arc A8 centre (-24.1631, 24.1712) radius 7.5 clockwise from (-18.0002, 28.4454) to (-18.0004, 19.8969)
  circle C14 centre (0, -70) radius 2.25
  circle C15 centre (0, -70) radius 5
  point P1 (0, 0)
  point P28 (0, 0)
  point P17 (-18.0002, 28.9864)
  point P29 (-18.0002, 28.9864)
  point P16 (17.9998, 28.9956)
  point P30 (17.9998, 28.9956)
  point P18 (-18.0012, -29.0136)
  point P31 (-18.0012, -29.0136)
  point P15 (17.9988, -29.0044)
  point P32 (17.9988, -29.0044)
  point P33 (17.9998, 28.9956)
  point P34 (-18.0012, -29.0136)
  point P41 (5.2344, 28.9924)
  point P42 (-5.2979, 28.9897)
  point P46 (17.9384, -29.0044)
  coincident P1 P28
  coincident P17 P29
  coincident P16 P30
  coincident P18 P31
  coincident P15 P32
  coincident P16 P33
  coincident P18 P34
  collinear L11 L12
  collinear L13 L15
  collinear L14 L15
  collinear L16 L17
  collinear L18 L19
  coincident L8 P41
  coincident L8 P42
  coincident L10 P46
  concentric C14 C15
  dimension "d559" diameter C13 = 26
extrude "Extrude107" new body sketch "Shim_For_Base" profile of L1 L2 L3 L4 L5 L6 C1 C2 C3 C4 L7 L8 L9 L10 C13 L17 L12 L19 L15 A5 A6 A4 A7 A8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 along normal blind 2 bodies "Shim For Base to Clear LED Holders"
extrude "Extrude108" new body sketch "Shim_For_Base" profile of C14 C15 along normal blind 4 bodies "PCB Mounting Washer 4mm"
extrude "Extrude109" new body sketch "Shim_For_Base" profile of C14 C15 along normal blind 8 bodies "PCB Mounting Washer 8mm"
named bodies: "Ball Detect", "Top", "Deck Section", "Under Deck Bracket", "Solenoid 22mm long", "Solenoid 37mm long", "Plunger", "Tactile Switch SR1112A", "Plunger Coupling", "Plunger (1)", "Base", "Base Lower", "Shim For Base to Clear LED Holders", "PCB Mounting Washer 4mm", "PCB Mounting Washer 8mm"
